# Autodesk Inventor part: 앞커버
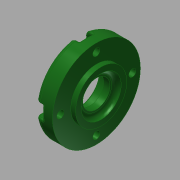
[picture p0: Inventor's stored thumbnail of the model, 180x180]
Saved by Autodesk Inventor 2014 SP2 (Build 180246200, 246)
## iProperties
Created: 2015-11
Part Number: 앞커버
Material: 알루미늄 6061
Document SubType Name: Modeling
Designer: mduedu
Density: 1 g/cm^3
Appearance: 매끄러움 - 짙은 산림 녹색
Author: mduedu
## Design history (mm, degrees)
sketch "스케치1"
  geometry: L1 (-7, 0)-(7, 0); L2 (-7, 0)-(-7, 27.5); L3 (-7, 27.5)-(4, 27.5); L4 (4, 27.5)-(4, 16); L5 (4, 16)-(7, 16); L6 (7, 16)-(7, 0); 2 further points
  constraints: 12 end point, 3 perpendicular, 2 parallel, 1 coincident, 1 horizontal, 1 midpoint
  dimensions: "d0" = 14 distance of L1.start L1.end; "d1" = 55 diameter of L3 L1; "d2" = 3 distance of L4.end L5.end; "d3" = 32 diameter of L5 L1
revolve "회전1" sketch "스케치1" stored, may be unused: angle "d4" = 90 deg
hole "구멍1" diameter "d7" = 25; stored, may be unused: countersink angle "d11" = 90 deg, drill point angle "d13" = 0 deg; dims "d5" = 10, "d6" = 10, "d8" = 6, "d9" = 4, "d10" = 2, "d12" = 3
hole "구멍2" diameter "d16" = 25; stored, may be unused: countersink angle "d20" = 90 deg, drill point angle "d22" = 0 deg; dims "d17" = 6, "d18" = 4, "d19" = 2, "d21" = 7, "d63" = 10, "d64" = 10
hole "구멍3" diameter "d25" = 17; stored, may be unused: countersink angle "d29" = 90 deg, drill point angle "d31" = 0 deg; dims "d23" = 10, "d24" = 10, "d26" = 6, "d27" = 4, "d28" = 2, "d30" = 4.2
chamfer "모따기1" distance "d32" = 0.6; stored, may be unused: second distance "d33" = 2, angle "d34" = 30 deg
fillet "모깎기1" dims "d35" = 0.3
fillet "모깎기2" dims "d36" = 3
fillet "모깎기3" dims "d37" = 3
sketch "스케치2" dims "d39" = 45
  geometry: C1 r 12.846 at (0, 0) reference; C2 r 24.5 at (0, 0) reference; 6 further points
  constraints: 2 vertical alignment, 1 coincident, 7 other
  dimensions: "d42" = 360 deg dimension on point (0, 0) point (0, 22.5) (derived)
sketch "스케치3"
  geometry: 8 further points
  constraints: 4 coincident
hole "구멍4" sketch "스케치3" at (-22.5, 0), (0, -22.5), (22.5, 0), (0, 22.5) diameter "d44" = 4.5; stored, may be unused: countersink angle "d48" = 90 deg, drill point angle "d50" = 0 deg; dims "d45" = 6, "d46" = 8, "d47" = 4.6, "d49" = 8
sketch "스케치4"
  geometry: L1 (-4, 0)-(-4, -4.708); L2 (4, 0)-(4, -4.708); A1 r 4 centre (0, 0) between (-4, 0) and (4, 0) reference; A2 r 27.5 centre (0, 22.5) between (-4, -4.708) and (4, -4.708) reference; 3 further points
  constraints: 4 end point, 4 point on circle, 2 tangent, 1 parallel, 1 vertical
extrude "돌출1" cut sketch "스케치4" stored distance "d51" = 0; taper "d52" = 0 deg
fillet "모깎기5" dims "d56" = 0.3
fillet "모깎기6" dims "d57" = 1
node "솔리드1"
pattern_circular "원형 패턴1" dims angle "d54" = 360 deg
